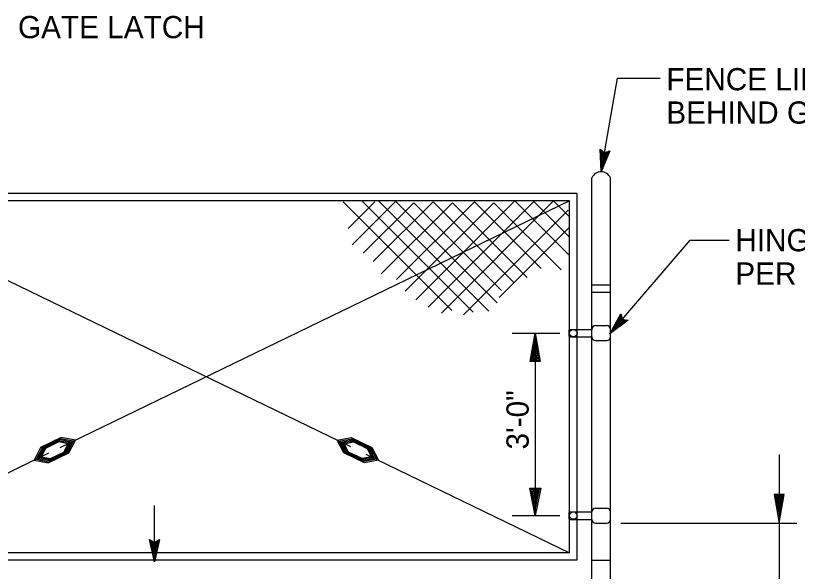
# Model space of a CAD drawing. Extents: x -123486 to -116575, y -107066 to -101122.
# Drawn here: x -118104.9 to -117894.1, y -102007.5 to -101857.5 of the extents above; entities that cross this region are included whole.
import ezdxf

# ---------------------------------------------------------------- set-up
doc = ezdxf.new("R2010")
doc.units = 0
for name, color, linetype in [('G-MARK', 7, 'Continuous'), ('G-TEXT', 7, 'Continuous'), ('Misc CnstDet(22)', 7, 'Continuous'), ('Nongeo Data(60)', 7, 'Continuous'), ('S-FNDN-PILE', 7, 'Continuous')]:
    doc.layers.add(name, color=color, linetype=linetype)

# ---------------------------------------------------------------- blocks, each defined once
blk = doc.blocks.new('ARROW')
at = {"layer": 'S-FNDN-PILE'}
blk.add_lwpolyline([(-0.002083, 0.000367), (-0.002083, -0.000367), (0, 0), (-0.002083, 0.000367), (-0.001983, 0), (-0.002017, -0.000267), (-0.00045, 0.000017), (-0.002017, 0.0003), (-0.001917, 0), (-0.001917, -0.000167), (-0.000833, 0.000017), (-0.001883, 0.0002), (-0.001867, -0.000117), (-0.001217, 0), (-0.001817, 0.0001), (-0.001767, -0.00005), (-0.00155, 0), (-0.002083, 0)], dxfattribs=at)

msp = doc.modelspace()

# ---------------------------------------------------------------- linework, layer by layer
at = {"layer": 'G-MARK'}
for p, q in [((-117942.59, -101874.36), (-117931.08, -101874.36)), ((-117946.98, -101899.66), (-117947.26, -101893.52)), ((-117947.26, -101893.52), (-117947.26, -101893.52)), ((-117947.26, -101893.52), (-117946.09, -101894.54)), ((-117944.63, -101893.98), (-117946.98, -101899.66)), ((-117946.75, -101898.29), (-117946.95, -101893.82)), ((-117945.02, -101894.13), (-117946.74, -101898.3)), ((-117946.51, -101896.94), (-117946.64, -101894.05)), ((-117945.42, -101894.3), (-117946.51, -101896.94)), ((-117946.27, -101895.58), (-117946.32, -101894.34)), ((-117945.79, -101894.41), (-117946.27, -101895.58)), ((-117946.09, -101894.54), (-117944.63, -101893.98)), ((-117944.63, -101893.98), (-117944.63, -101893.98)), ((-117946.98, -101899.66), (-117946.98, -101899.66)), ((-117944.6, -101943.45), (-117941.71, -101938.03)), ((-117939.68, -101939.76), (-117944.6, -101943.45)), ((-117943.7, -101942.39), (-117941.59, -101938.44)), ((-117940.09, -101939.7), (-117943.7, -101942.4)), ((-117942.8, -101941.35), (-117941.44, -101938.8)), ((-117940.52, -101939.64), (-117942.8, -101941.35)), ((-117941.9, -101940.3), (-117941.32, -101939.21)), ((-117940.9, -101939.55), (-117941.9, -101940.3)), ((-117941.71, -101938.03), (-117941.71, -101938.03)), ((-117941.71, -101938.03), (-117941.22, -101939.5)), ((-117941.22, -101939.5), (-117939.68, -101939.76)), ((-117939.68, -101939.76), (-117939.68, -101939.76)), ((-117971, -101943.2), (-117958.16, -101943.2)), ((-117964.77, -101943.2), (-117964.77, -101957.96)), ((-117944.6, -101943.45), (-117944.6, -101943.45)), ((-117964.77, -101957.96), (-117964.77, -101992.49)), ((-117898.96, -101975.97), (-117898.96, -102027.09)), ((-118067.49, -102004.95), (-118067.49, -101989.73)), ((-117971, -101992.49), (-117958.16, -101992.49)), ((-117941.65, -101994.5), (-117894.23, -101994.5))]:
    msp.add_line(p, q, dxfattribs=at)
for points in [[(-117946.98, -101899.66), (-117942.59, -101874.36), (-117942.59, -101874.36)], [(-117944.6, -101943.45), (-117923.01, -101918.15), (-117912.46, -101918.15)]]:
    msp.add_lwpolyline(points, dxfattribs=at)
at = {"layer": 'G-TEXT'}
for p, q in [((-118067.49, -102004.95), (-118068.82, -101998.95)), ((-118068.82, -101998.95), (-118068.82, -101998.95)), ((-118068.82, -101998.95), (-118067.49, -101999.75)), ((-118067.5, -102003.56), (-118068.46, -101999.19)), ((-118067.49, -102002.19), (-118068.12, -101999.37)), ((-118067.49, -102000.81), (-118067.76, -101999.6)), ((-118067.49, -101999.75), (-118066.15, -101998.95)), ((-118066.15, -101998.95), (-118067.49, -102004.95)), ((-118066.51, -101999.17), (-118067.49, -102003.57)), ((-118066.87, -101999.41), (-118067.49, -102002.19)), ((-118067.21, -101999.58), (-118067.49, -102000.81)), ((-118066.15, -101998.95), (-118066.15, -101998.95)), ((-118067.49, -102004.95), (-118067.49, -102004.95))]:
    msp.add_line(p, q, dxfattribs=at)
for points in [[(-117963.4, -101950.89), (-117966.13, -101950.89), (-117964.77, -101943.2), (-117963.4, -101950.89), (-117964.77, -101950.52), (-117965.76, -101950.65), (-117964.71, -101944.94), (-117963.65, -101950.65), (-117964.77, -101950.27), (-117965.39, -101950.27), (-117964.71, -101946.3), (-117964.02, -101950.15), (-117965.2, -101950.09), (-117964.77, -101947.73), (-117964.4, -101949.9), (-117964.95, -101949.71), (-117964.77, -101948.97), (-117964.77, -101950.89)], [(-117897.6, -101986.81), (-117900.33, -101986.81), (-117898.96, -101994.5), (-117897.6, -101986.81), (-117898.96, -101987.18), (-117899.96, -101987.06), (-117898.9, -101992.76), (-117897.85, -101987.06), (-117898.96, -101987.43), (-117899.58, -101987.43), (-117898.9, -101991.4), (-117898.22, -101987.55), (-117899.4, -101987.62), (-117898.96, -101989.97), (-117898.59, -101987.8), (-117899.15, -101987.99), (-117898.96, -101988.73), (-117898.96, -101986.81)]]:
    msp.add_lwpolyline(points, dxfattribs=at)
at = {"layer": 'Nongeo Data(60)'}
for p, q in [((-117949.48, -101988.23), (-117949.48, -101901.31)), ((-117944.48, -101988.23), (-117944.48, -101901.31)), ((-117953.48, -101905.5), (-118153.48, -101905.5)), ((-117953.48, -101930.83), (-117953.48, -101905.5)), ((-117955.48, -101907.5), (-118151.48, -101907.5)), ((-118151.48, -101907.5), (-118014.61, -101973.84)), ((-117955.48, -101907.5), (-118093.05, -101974.18)), ((-117987.24, -101937.08), (-118016.55, -101907.77)), ((-118015.24, -101915.01), (-118008.01, -101907.77)), ((-118014.18, -101919.4), (-118002.31, -101907.53)), ((-117981.54, -101937.56), (-118011.57, -101907.53)), ((-118011.21, -101921.66), (-117997.56, -101908.01)), ((-118008.48, -101923.91), (-117992.34, -101907.77)), ((-117977.27, -101937.32), (-118007.06, -101907.53)), ((-118006.34, -101927.23), (-117987.12, -101908.01)), ((-117975.02, -101935.06), (-118002.55, -101907.53)), ((-118002.19, -101928.78), (-117981.19, -101907.77)), ((-117999.82, -101931.86), (-117975.97, -101908.01)), ((-117973.83, -101931.74), (-117997.56, -101908.01)), ((-117996.97, -101934.23), (-117970.27, -101907.53)), ((-117993.63, -101936.17), (-117964.88, -101907.42)), ((-117970.63, -101929.49), (-117992.34, -101907.77)), ((-117990.09, -101937.79), (-117959.83, -101907.53)), ((-117966.95, -101928.18), (-117987.12, -101908.01)), ((-117963.15, -101925.81), (-117981.19, -101907.77)), ((-117957.81, -101926.16), (-117975.97, -101908.01)), ((-117955.61, -101922.19), (-117970.27, -101907.53)), ((-117955.48, -101917.34), (-117965.05, -101907.77)), ((-117955.72, -101911.64), (-117959.83, -101907.53)), ((-117955.48, -101930.47), (-117955.48, -101907.5)), ((-117984.15, -101938.27), (-117955.88, -101909.99)), ((-117974.54, -101933.64), (-117955.69, -101914.79)), ((-117955.48, -102002.5), (-117955.48, -101930.47)), ((-117953.48, -102004.5), (-117953.48, -101930.83)), ((-117949.48, -101930.2), (-117944.48, -101930.2)), ((-117949.48, -101932.2), (-117944.48, -101932.2)), ((-117953.48, -101942.2), (-117953.48, -101938.93)), ((-117949.48, -101941.18), (-117949.48, -101938.93)), ((-117944.48, -101941.2), (-117944.48, -101938.93)), ((-117949.48, -101946.85), (-117949.48, -101941.18)), ((-117948.48, -101941.2), (-117945.48, -101941.2)), ((-117944.48, -101946.85), (-117944.48, -101941.15)), ((-117955.61, -101942.2), (-117949.48, -101942.2)), ((-117949.48, -101944.2), (-117949.48, -101942.2)), ((-117944.48, -101944.2), (-117944.48, -101942.2)), ((-117955.61, -101944.2), (-117949.48, -101944.2)), ((-117953.48, -101946.85), (-117953.48, -101944.2)), ((-117948.48, -101945.2), (-117945.48, -101945.2)), ((-118092.63, -101971.42), (-118098.21, -101974.13)), ((-118088.83, -101972.14), (-118092.63, -101971.42)), ((-118018.2, -101972.11), (-118014.4, -101971.39)), ((-118014.4, -101971.39), (-118008.82, -101974.1)), ((-118092.81, -101971.76), (-118097.83, -101974.2)), ((-118092.97, -101972.07), (-118097.49, -101974.27)), ((-118093.12, -101972.35), (-118097.18, -101974.33)), ((-118093.25, -101972.6), (-118096.91, -101974.38)), ((-118090.76, -101973.08), (-118093.25, -101972.6)), ((-118090.35, -101972.88), (-118093.12, -101972.35)), ((-118089.9, -101972.66), (-118092.97, -101972.07)), ((-118089.39, -101972.41), (-118092.81, -101971.76)), ((-118091.92, -101975.33), (-118090.76, -101973.08)), ((-118091.64, -101975.38), (-118090.35, -101972.88)), ((-118091.34, -101975.44), (-118089.9, -101972.66)), ((-118090.99, -101975.5), (-118089.39, -101972.41)), ((-118090.61, -101975.57), (-118088.83, -101972.14)), ((-118016.42, -101975.55), (-118018.2, -101972.11)), ((-118017.64, -101972.39), (-118014.22, -101971.74)), ((-118016.04, -101975.48), (-118017.64, -101972.39)), ((-118017.14, -101972.64), (-118014.06, -101972.05)), ((-118015.7, -101975.42), (-118017.14, -101972.64)), ((-118016.68, -101972.87), (-118013.92, -101972.34)), ((-118015.39, -101975.37), (-118016.68, -101972.87)), ((-118016.28, -101973.07), (-118013.79, -101972.59)), ((-118015.11, -101975.32), (-118016.28, -101973.07)), ((-118014.22, -101971.74), (-118009.2, -101974.18)), ((-118014.06, -101972.05), (-118009.54, -101974.25)), ((-118013.92, -101972.34), (-118009.85, -101974.31)), ((-118013.79, -101972.59), (-118010.13, -101974.37)), ((-118096.07, -101975.64), (-118151.48, -102002.5)), ((-118098.21, -101974.13), (-118099.98, -101977.56)), ((-118097.83, -101974.2), (-118099.43, -101977.29)), ((-118097.49, -101974.27), (-118098.93, -101977.05)), ((-118097.18, -101974.33), (-118098.48, -101976.83)), ((-118096.91, -101974.38), (-118098.07, -101976.63)), ((-118096.19, -101978.28), (-118090.61, -101975.57)), ((-118096.01, -101977.94), (-118090.99, -101975.5)), ((-118095.85, -101977.63), (-118091.34, -101975.44)), ((-118095.71, -101977.36), (-118091.64, -101975.38)), ((-118095.58, -101977.11), (-118091.92, -101975.33)), ((-118010.84, -101978.26), (-118016.42, -101975.55)), ((-118011.02, -101977.92), (-118016.04, -101975.48)), ((-118011.18, -101977.62), (-118015.7, -101975.42)), ((-118011.33, -101977.34), (-118015.39, -101975.37)), ((-118011.45, -101977.1), (-118015.11, -101975.32)), ((-118010.13, -101974.37), (-118008.96, -101976.62)), ((-118009.85, -101974.31), (-118008.56, -101976.82)), ((-118009.54, -101974.25), (-118008.1, -101977.03)), ((-118009.2, -101974.18), (-118007.6, -101977.27)), ((-118008.82, -101974.1), (-118007.05, -101977.54)), ((-118099.98, -101977.56), (-118096.19, -101978.28)), ((-118099.43, -101977.29), (-118096.01, -101977.94)), ((-118098.93, -101977.05), (-118095.85, -101977.63)), ((-118098.48, -101976.83), (-118095.71, -101977.36)), ((-118098.07, -101976.63), (-118095.58, -101977.11)), ((-118008.96, -101976.62), (-118011.45, -101977.1)), ((-118008.56, -101976.82), (-118011.33, -101977.34)), ((-118008.1, -101977.03), (-118011.18, -101977.62)), ((-118007.6, -101977.27), (-118011.02, -101977.92)), ((-118007.05, -101977.54), (-118010.84, -101978.26)), ((-118010.43, -101975.86), (-117955.48, -102002.5)), ((-117949.48, -101990.48), (-117949.48, -101988.23)), ((-117949.48, -101996.14), (-117949.48, -101988.23)), ((-117944.48, -101990.49), (-117944.48, -101988.23)), ((-117944.48, -101996.14), (-117944.48, -101988.23)), ((-117955.61, -101991.5), (-117949.59, -101991.5)), ((-117949.48, -101996.14), (-117949.48, -101990.48)), ((-117949.48, -101993.5), (-117949.48, -101991.5)), ((-117948.48, -101990.5), (-117945.48, -101990.5)), ((-117944.48, -101996.14), (-117944.48, -101990.45)), ((-117944.48, -101993.5), (-117944.48, -101991.5)), ((-117955.61, -101993.5), (-117949.48, -101993.5)), ((-117948.48, -101994.5), (-117945.48, -101994.5)), ((-117949.48, -102055.5), (-117949.48, -101996.14)), ((-117944.48, -102055.5), (-117944.48, -101996.14)), ((-117955.48, -102002.5), (-118151.48, -102002.5)), ((-117953.48, -102004.5), (-118153.48, -102004.5)), ((-117949.48, -102004.5), (-117944.48, -102004.5))]:
    msp.add_line(p, q, dxfattribs=at)
for centre in [(-117954.48, -101943.21), (-117954.49, -101992.49)]:
    msp.add_circle(centre, 1, dxfattribs=at)
for centre, radius, start, end in [((-117946.98, -101902.38), 2.72, 23.2888, 156.7112), ((-117948.48, -101942.2), 1, 90, 180), ((-117945.48, -101942.2), 1, 0, 90), ((-117948.48, -101944.2), 1, 180, 270), ((-117945.48, -101944.2), 1, 270, 0), ((-117948.48, -101991.5), 1, 90, 180), ((-117945.48, -101991.5), 1, 0, 90), ((-117948.48, -101993.5), 1, 180, 270), ((-117945.48, -101993.5), 1, 270, 0)]:
    msp.add_arc(centre, radius, start, end, dxfattribs=at)
for centre in [(-117955.61, -101943.2), (-117955.61, -101992.5)]:
    msp.add_ellipse(centre, major_axis=(0, -1), ratio=0.098201, start_param=3.141593, end_param=6.283185, dxfattribs=at)

# ---------------------------------------------------------------- block references
at = {"layer": 'G-TEXT', "xscale": 3571.703056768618, "yscale": -4058.0876675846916, "rotation": -90}
msp.add_blockref('ARROW', (-117964.77, -101992.49), dxfattribs=at)

# ---------------------------------------------------------------- texts
at = {"layer": 'Misc CnstDet(22)'}
for s, p in [('GATE LATCH', (-118104.31, -101863.6)), ('FENCE LINE EXTENDS', (-117929.41, -101877.67)), ('BEHIND GATE POST', (-117929.41, -101886.67)), ('HINGE TYPE', (-117910.79, -101921.13)), ('PER SPECIFICATIONS', (-117910.79, -101930.13))]:
    msp.add_text(s, height=6, dxfattribs=at).set_placement(p)
msp.add_text('3\'-0"', height=6, rotation=90, dxfattribs=at).set_placement((-117966.54, -101974.64))

doc.saveas('drawing.dxf')
